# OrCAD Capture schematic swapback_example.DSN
size C
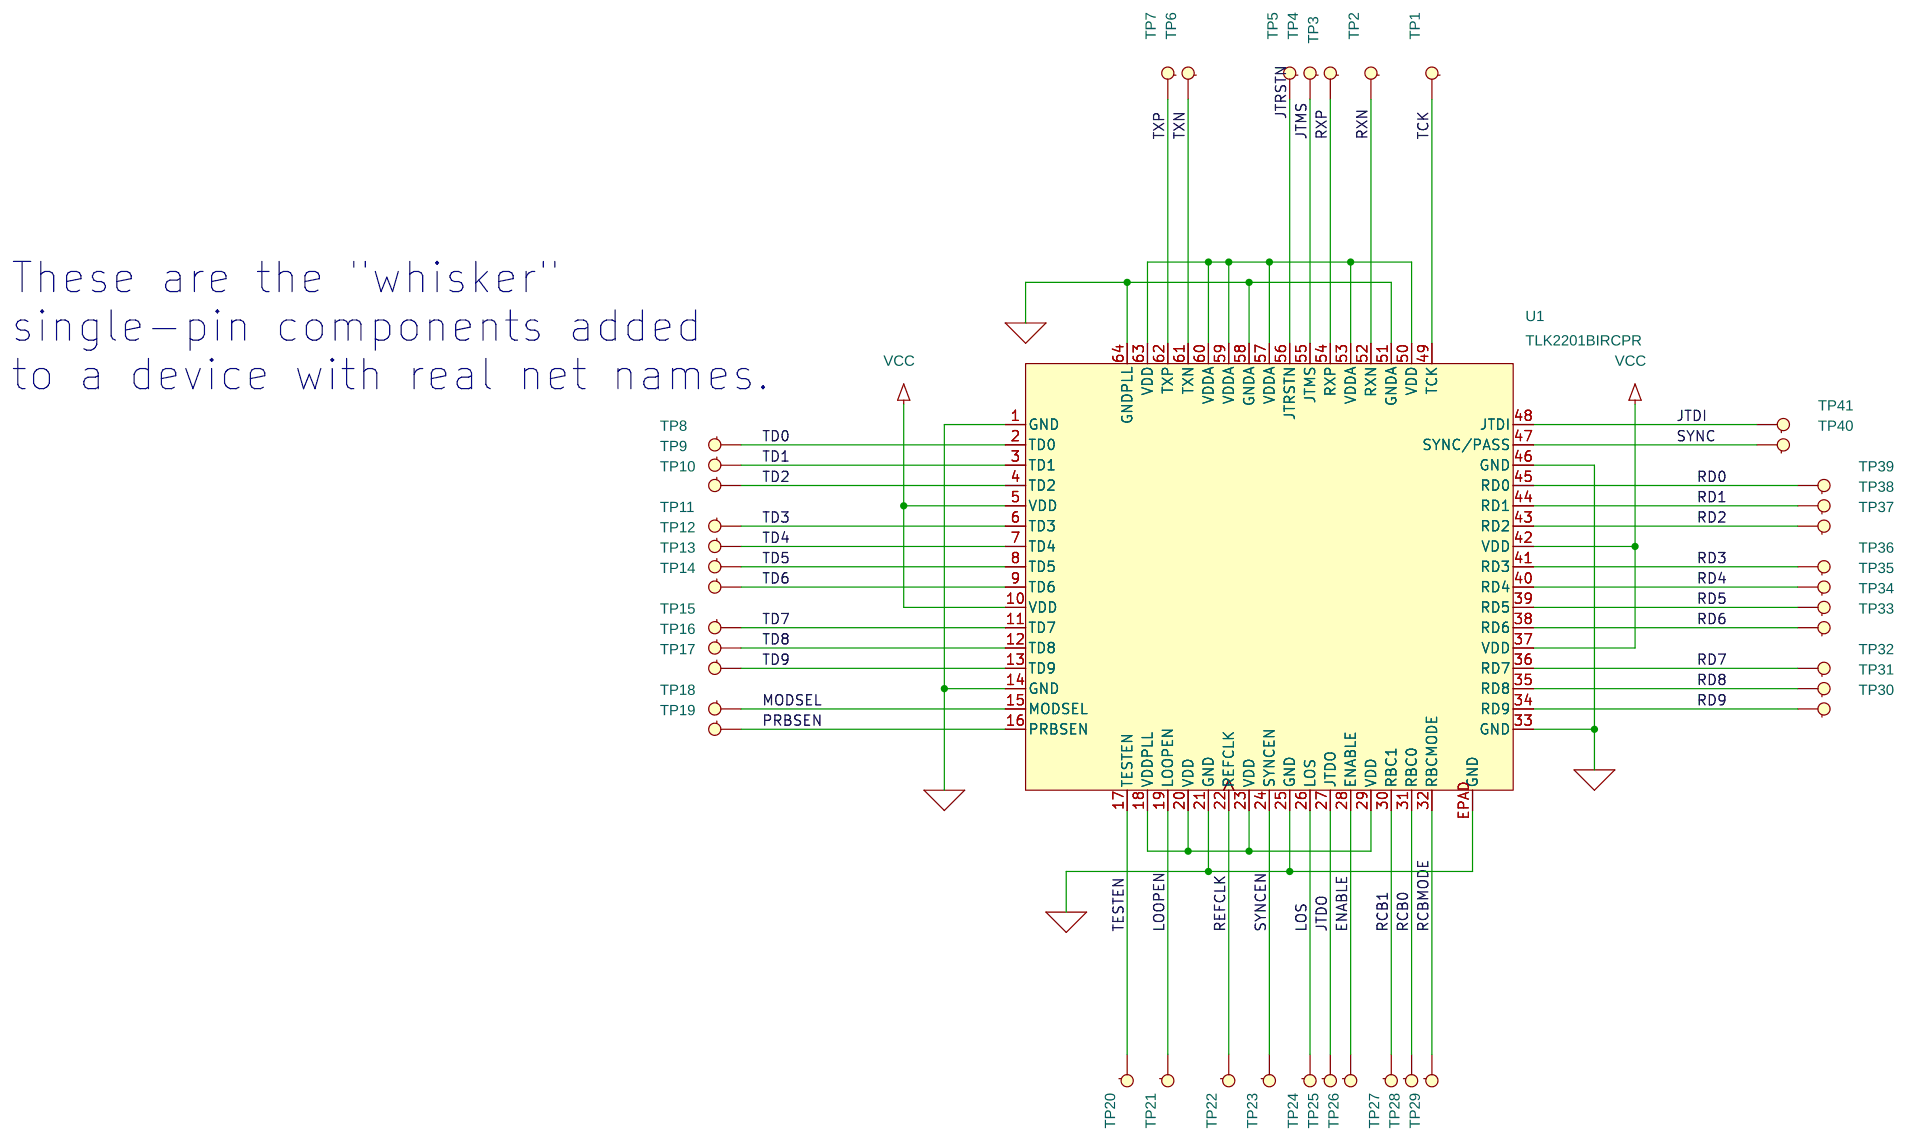
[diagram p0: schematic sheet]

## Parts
TP1  TP .25mm noV  [TESTPAD_p25MM_NOVIA]
TP2  TP .25mm noV  [TESTPAD_p25MM_NOVIA]
TP3  TP .25mm noV  [TESTPAD_p25MM_NOVIA]
TP4  TP .25mm noV  [TESTPAD_p25MM_NOVIA]
TP5  TP .25mm noV  [TESTPAD_p25MM_NOVIA]
TP6  TP .25mm noV  [TESTPAD_p25MM_NOVIA]
TP7  TP .25mm noV  [TESTPAD_p25MM_NOVIA]
TP8  TP .25mm noV  [TESTPAD_p25MM_NOVIA]
TP9  TP .25mm noV  [TESTPAD_p25MM_NOVIA]
TP10  TP .25mm noV  [TESTPAD_p25MM_NOVIA]
TP11  TP .25mm noV  [TESTPAD_p25MM_NOVIA]
TP12  TP .25mm noV  [TESTPAD_p25MM_NOVIA]
TP13  TP .25mm noV  [TESTPAD_p25MM_NOVIA]
TP14  TP .25mm noV  [TESTPAD_p25MM_NOVIA]
TP15  TP .25mm noV  [TESTPAD_p25MM_NOVIA]
TP16  TP .25mm noV  [TESTPAD_p25MM_NOVIA]
TP17  TP .25mm noV  [TESTPAD_p25MM_NOVIA]
TP18  TP .25mm noV  [TESTPAD_p25MM_NOVIA]
TP19  TP .25mm noV  [TESTPAD_p25MM_NOVIA]
TP20  TP .25mm noV  [TESTPAD_p25MM_NOVIA]
TP21  TP .25mm noV  [TESTPAD_p25MM_NOVIA]
TP22  TP .25mm noV  [TESTPAD_p25MM_NOVIA]
TP23  TP .25mm noV  [TESTPAD_p25MM_NOVIA]
TP24  TP .25mm noV  [TESTPAD_p25MM_NOVIA]
TP25  TP .25mm noV  [TESTPAD_p25MM_NOVIA]
TP26  TP .25mm noV  [TESTPAD_p25MM_NOVIA]
TP27  TP .25mm noV  [TESTPAD_p25MM_NOVIA]
TP28  TP .25mm noV  [TESTPAD_p25MM_NOVIA]
TP29  TP .25mm noV  [TESTPAD_p25MM_NOVIA]
TP30  TP .25mm noV  [TESTPAD_p25MM_NOVIA]
TP31  TP .25mm noV  [TESTPAD_p25MM_NOVIA]
TP32  TP .25mm noV  [TESTPAD_p25MM_NOVIA]
TP33  TP .25mm noV  [TESTPAD_p25MM_NOVIA]
TP34  TP .25mm noV  [TESTPAD_p25MM_NOVIA]
TP35  TP .25mm noV  [TESTPAD_p25MM_NOVIA]
TP36  TP .25mm noV  [TESTPAD_p25MM_NOVIA]
TP37  TP .25mm noV  [TESTPAD_p25MM_NOVIA]
TP38  TP .25mm noV  [TESTPAD_p25MM_NOVIA]
TP39  TP .25mm noV  [TESTPAD_p25MM_NOVIA]
TP40  TP .25mm noV  [TESTPAD_p25MM_NOVIA]
TP41  TP .25mm noV  [TESTPAD_p25MM_NOVIA]
U1  TLK2201BIRCPR  [QFP50P1200X1200X120-65N_junk]

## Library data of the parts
TP1-TP41 = MINI_TP: TESTPAD NO-VIA 0.25MM; PART_NUMBER: CONN_NL_TP_P25MM_NO-VIA
U1 = TLK2201B: IC ETHRNT XCVR 1.2-1.6GBPS 64HVQ; ALT_SYMBOL: DRQFN65P600X600X80-52N_JUNK; PART_NUMBER: TMP-804

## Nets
GND_SIGNAL: U1.1(GND) U1.14(GND) U1.21(GND) U1.25(GND) U1.33(GND) U1.46(GND) U1.51(GNDA) U1.58(GNDA) U1.64(GNDPLL) U1.EPAD(GND)
VCC: U1.5(VDD) U1.10(VDD) U1.37(VDD) U1.42(VDD)
ENABLE: TP26.1 U1.28(ENABLE)
JTDI: TP41.1 U1.48(JTDI)
JTDO: TP25.1 U1.27(JTDO)
JTMS: TP4.1 U1.55(JTMS)
JTRSTN: TP5.1 U1.56(JTRSTN)
LOOPEN: TP21.1 U1.19(LOOPEN)
LOS: TP24.1 U1.26(LOS)
MODSEL: TP18.1 U1.15(MODSEL)
PRBSEN: TP19.1 U1.16(PRBSEN)
RCB0: TP28.1 U1.31(RBC0)
RCB1: TP27.1 U1.30(RBC1)
RCBMODE: TP29.1 U1.32(RBCMODE)
RD0: TP39.1 U1.45(RD0)
RD1: TP38.1 U1.44(RD1)
RD2: TP37.1 U1.43(RD2)
RD3: TP36.1 U1.41(RD3)
RD4: TP35.1 U1.40(RD4)
RD5: TP34.1 U1.39(RD5)
RD6: TP33.1 U1.38(RD6)
RD7: TP32.1 U1.36(RD7)
RD8: TP31.1 U1.35(RD8)
RD9: TP30.1 U1.34(RD9)
REFCLK: TP22.1 U1.22(REFCLK)
RXN: TP2.1 U1.52(RXN)
RXP: TP3.1 U1.54(RXP)
SYNC: TP40.1 U1.47(SYNC/PASS)
SYNCEN: TP23.1 U1.24(SYNCEN)
TCK: TP1.1 U1.49(TCK)
TD0: TP8.1 U1.2(TD0)
TD1: TP9.1 U1.3(TD1)
TD2: TP10.1 U1.4(TD2)
TD3: TP11.1 U1.6(TD3)
TD4: TP12.1 U1.7(TD4)
TD5: TP13.1 U1.8(TD5)
TD6: TP14.1 U1.9(TD6)
TD7: TP15.1 U1.11(TD7)
TD8: TP16.1 U1.12(TD8)
TD9: TP17.1 U1.13(TD9)
TESTEN: TP20.1 U1.17(TESTEN)
TXN: TP6.1 U1.61(TXN)
TXP: TP7.1 U1.62(TXP)
N09924: U1.50(VDD) U1.53(VDDA) U1.57(VDDA) U1.59(VDDA) U1.60(VDDA) U1.63(VDD)
N10926: U1.18(VDDPLL) U1.20(VDD) U1.23(VDD) U1.29(VDD)

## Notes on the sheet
- These are the "whisker"
  single-pin components added
  to a device with real net names.
